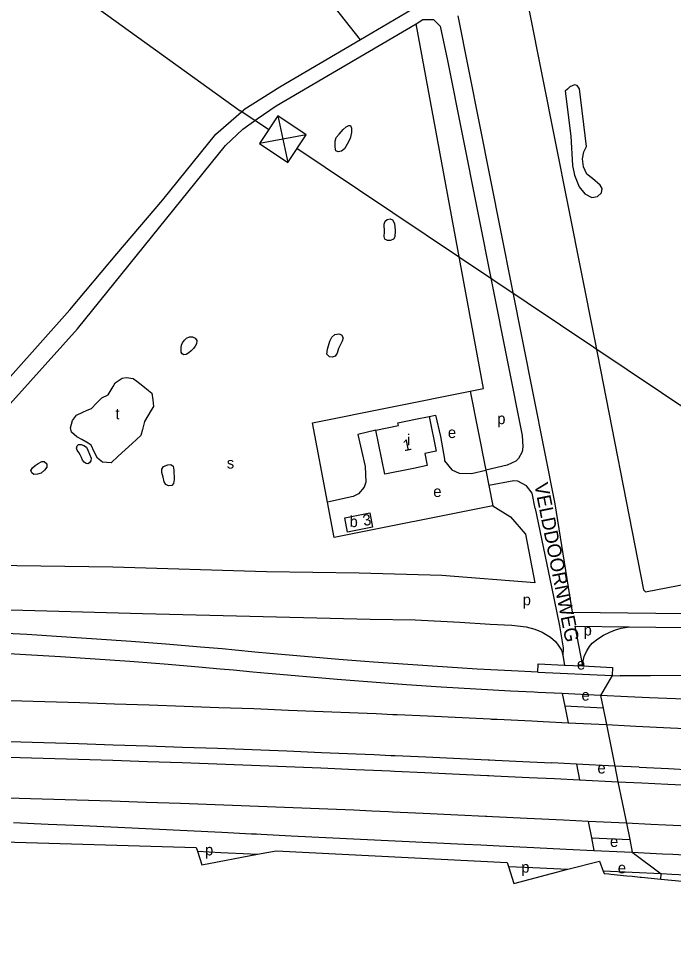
# Model space of a CAD drawing. Extents: x 160204 to 161526, y 379528 to 381793.
# Drawn here: x 160776.3 to 161011.9, y 379542.4 to 379877.4 of the extents above; entities that cross this region are included whole.
import ezdxf

# ---------------------------------------------------------------- set-up
doc = ezdxf.new("R2010")
doc.units = 0
for name, color, linetype in [('BLT_Basislijn', 7, 'Continuous'), ('BLT_Bebouwing', 7, 'Continuous'), ('BLT_Centroide', 7, 'Continuous'), ('BLT_Gemeentegrens', 7, 'Continuous'), ('BLT_Hoogspanningsmast_en_leidingen', 7, 'Continuous'), ('BLT_Huisnummer', 7, 'Continuous'), ('BLT_Straatnaam', 7, 'Continuous'), ('BLT_Vlakafsluiter', 7, 'Continuous')]:
    doc.layers.add(name, color=color, linetype=linetype)

msp = doc.modelspace()

# ---------------------------------------------------------------- linework, layer by layer
at = {"layer": 'BLT_Basislijn'}
for p, q in [((160934.43, 379878.45), (160969.28, 379702.73)), ((160943.64, 379744.33), (160919.34, 379875.6)), ((160810.28, 379744.96), (160811.1, 379746.33)), ((160811.1, 379746.33), (160813.58, 379747.98)), ((160813.58, 379747.98), (160815.17, 379748.29)), ((160815.17, 379748.29), (160817.56, 379747.91)), ((160817.56, 379747.91), (160818.86, 379746.88)), ((160818.86, 379746.88), (160820.95, 379745.23)), ((160808.56, 379742.07), (160810.28, 379744.96)), ((160820.95, 379745.23), (160823.04, 379743.58)), ((160823.04, 379743.58), (160824.29, 379742.6)), ((160824.29, 379742.6), (160824.57, 379740.22)), ((160882.02, 379731.98), (160938.84, 379743.37)), ((160938.84, 379743.37), (160943.64, 379744.33)), ((160938.84, 379743.37), (160944.44, 379714.95)), ((160804.37, 379739.05), (160806.22, 379740.98)), ((160806.22, 379740.98), (160808.56, 379742.07)), ((160824.57, 379740.22), (160824.84, 379737.84)), ((160799.43, 379735.75), (160800.98, 379736.44)), ((160800.98, 379736.44), (160802.53, 379737.12)), ((160802.53, 379737.12), (160804.37, 379739.05)), ((160824.02, 379736.44), (160822.82, 379734.41)), ((160824.84, 379737.84), (160824.02, 379736.44)), ((160795, 379730.16), (160795.65, 379732.73)), ((160795.65, 379732.73), (160797.09, 379734.72)), ((160797.09, 379734.72), (160799.43, 379735.75)), ((160822.82, 379734.41), (160821.63, 379732.38)), ((160795.3, 379728.61), (160795, 379730.16)), ((160820.86, 379729.5), (160820.28, 379727.34)), ((160821.63, 379732.38), (160820.86, 379729.5)), ((160887.41, 379703.39), (160882.02, 379731.98)), ((160797.23, 379726.89), (160795.3, 379728.61)), ((160799.08, 379725.97), (160797.23, 379726.89)), ((160801.35, 379724.56), (160799.08, 379725.97)), ((160818.73, 379725.93), (160817.18, 379724.52)), ((160820.28, 379727.34), (160818.73, 379725.93)), ((160802.45, 379723.87), (160801.35, 379724.56)), ((160803.55, 379721.54), (160802.45, 379723.87)), ((160817.18, 379724.52), (160814.64, 379722.21)), ((160804.65, 379719.2), (160803.55, 379721.54)), ((160806.5, 379717.83), (160804.65, 379719.2)), ((160812.1, 379719.9), (160809.56, 379717.59)), ((160814.64, 379722.21), (160812.1, 379719.9)), ((160809.56, 379717.59), (160806.5, 379717.83)), ((160944.44, 379714.95), (160945.54, 379709.34)), ((160945.54, 379709.34), (160946.98, 379702.01)), ((160969.28, 379702.73), (160975.53, 379663.75)), ((160976.43, 379658.74), (160979.24, 379644.43)), ((160963.12, 379642.17), (160989.94, 379641.02)), ((160989.94, 379641.02), (160992.79, 379640.9)), ((160971.9, 379634.47), (160963.12, 379634.9)), ((160971.9, 379634.47), (160972.82, 379629.92)), ((160985.69, 379633.8), (160971.9, 379634.47)), ((160995.45, 379633.32), (160985.69, 379633.8)), ((160985.69, 379633.8), (160986.62, 379629.25)), ((160986.62, 379629.25), (160972.82, 379629.92)), ((160972.82, 379629.92), (160974.02, 379624)), ((160986.62, 379629.25), (160987.82, 379623.33)), ((160965.04, 379624.44), (160974.02, 379624)), ((160974.02, 379624), (160987.82, 379623.33)), ((160987.82, 379623.33), (160996.42, 379622.91)), ((160977.05, 379609.09), (160968.23, 379609.52)), ((160977.05, 379609.09), (160978.21, 379603.42)), ((160990.85, 379608.41), (160977.05, 379609.09)), ((160999.68, 379607.98), (160990.85, 379608.41)), ((160990.85, 379608.41), (160992, 379602.75)), ((160969.11, 379603.87), (160978.21, 379603.42)), ((160978.21, 379603.42), (160992, 379602.75)), ((160992, 379602.75), (161000.6, 379602.33)), ((160981.24, 379588.51), (160972.36, 379588.94)), ((160981.24, 379588.51), (160982.44, 379582.59)), ((160995.03, 379587.84), (160981.24, 379588.51)), ((161003.8, 379587.41), (160995.03, 379587.84)), ((160995.03, 379587.84), (160996.23, 379581.92)), ((160982.44, 379582.59), (160996.23, 379581.92)), ((160982.44, 379582.59), (160983.36, 379578.04)), ((160996.23, 379581.92), (160997.16, 379577.37)), ((160973.37, 379578.53), (160983.36, 379578.04)), ((160983.36, 379578.04), (160997.16, 379577.37)), ((160997.16, 379577.37), (161005.73, 379576.95)), ((161007.53, 379569.61), (160986.7, 379570.62))]:
    msp.add_line(p, q, dxfattribs=at)
for points in [[(160899.34, 379869.75), (160838.56, 379946.96), (160831.95, 379953.52), (160783.95, 379999.78)], [(160916.02, 379935.16), (160925.3, 379888.11), (160925.28, 379886.57), (160924.22, 379884.76), (160921.8, 379882.93), (160899.34, 379869.75)], [(160959.88, 379880.87), (160983.6, 379762), (161001.22, 379671.83), (161001.95, 379671.12), (161047.14, 379679.9)], [(160919.34, 379875.6), (160921.8, 379877.04), (160925.63, 379877.11), (160928, 379874.75), (160930.71, 379862.36), (160957.56, 379727.33), (160957.79, 379723.3), (160957.55, 379721.48), (160956.15, 379719.16), (160955.2, 379718.2), (160952.08, 379716.73), (160944.44, 379714.95)], [(160862.11, 379841.36), (160868.99, 379846.06), (160919.34, 379875.6)], [(160899.34, 379869.75), (160870.36, 379852.74), (160857.41, 379844.61)], [(160686.29, 379682.82), (160737.48, 379711.91), (160746.25, 379719.03), (160752.91, 379725.65), (160794.74, 379772.59), (160811.69, 379792.71), (160828.15, 379812.23), (160847.28, 379835.89), (160857.41, 379844.61)], [(160714.73, 379691.69), (160729.47, 379699.34), (160740.52, 379706.54), (160746.8, 379711.17), (160757.2, 379721.03), (160797.44, 379765.72), (160850.78, 379831.75), (160856.96, 379837.67), (160862.11, 379841.36)], [(160924.04, 379734.22), (160926.38, 379734.71), (160928.09, 379727.02), (160929.54, 379718.81), (160929.59, 379718.22), (160932.2, 379714.99), (160934.9, 379713.77), (160939.27, 379713.74), (160944.44, 379714.95)], [(160904.87, 379729.29), (160898.39, 379727.75), (160900.97, 379716.2), (160901.23, 379710.57), (160900.65, 379708.82), (160898.58, 379706.34), (160896.74, 379705.38), (160887.41, 379703.39)], [(160962.24, 379701.07), (160961.18, 379706.59), (160959.08, 379709.32), (160955.99, 379710.92), (160954.56, 379711.03), (160945.54, 379709.34)], [(160946.98, 379702.01), (160889.82, 379690.64), (160887.41, 379703.39)], [(160946.98, 379702.01), (160953.36, 379698.08), (160958.67, 379691.87), (160962.04, 379674.37)], [(160962.24, 379701.07), (160968.14, 379672.96), (160970.93, 379658.91), (160972.28, 379650.99), (160972.17, 379648.23)], [(160962.04, 379674.37), (160928.58, 379676.98), (160898.9, 379677.88), (160865.48, 379678.32), (160810.17, 379679.97), (160775.69, 379680.42), (160734.32, 379681.17), (160697.47, 379682.72)], [(160975.53, 379663.75), (161005.65, 379663.43), (161049.95, 379662.91), (161061.02, 379662.97), (161065.81, 379663.17), (161069.15, 379663.77), (161073.72, 379664.97), (161078.31, 379666.46), (161085.6, 379669.78), (161098.15, 379675.54), (161108.55, 379680.23)], [(160563.17, 379668.7), (160589.01, 379668.81), (160613.98, 379668.38), (160632.18, 379668.08), (160662.14, 379666.95), (160686.53, 379666.48), (160709.05, 379665.91), (160737.95, 379665.26), (160769.1, 379664.77), (160820.86, 379663.28), (160849.87, 379662.62), (160902.88, 379661.28), (160918.99, 379661), (160935.1, 379660.15), (160946.02, 379659.49), (160953.84, 379659.12), (160958.98, 379658.56), (160962.1, 379657.7), (160964.74, 379656.63), (160967.7, 379654.85), (160969.48, 379653.29), (160970.5, 379651.89), (160971.63, 379650.06), (160972.17, 379648.23)], [(160963.12, 379642.17), (160953.74, 379642.63), (160941.3, 379643.32), (160928.86, 379644.08), (160916.43, 379644.91), (160904, 379645.81), (160891.57, 379646.79), (160879.16, 379647.83), (160866.75, 379648.94), (160861.29, 379649.45), (160854.29, 379650.11), (160849.51, 379650.54), (160841.81, 379651.22), (160829.31, 379652.26), (160816.81, 379653.23), (160804.3, 379654.13), (160791.79, 379654.96), (160779.28, 379655.72), (160766.76, 379656.4), (160754.23, 379657.02), (160741.71, 379657.56), (160735.68, 379657.79)], [(160976.43, 379658.74), (160996.04, 379658.53)], [(160979.24, 379644.43), (160979.45, 379646.22), (160979.88, 379647.78), (160980.68, 379649.6), (160981.76, 379651.42), (160982.77, 379652.68), (160984.8, 379654.18), (160986.8, 379655.51), (160989.05, 379656.61), (160991.06, 379657.38), (160993.12, 379657.98), (160996.04, 379658.53)], [(160996.04, 379658.53), (161005.59, 379658.43), (161049.93, 379657.91), (161061.14, 379657.97), (161066.36, 379658.19)], [(160963.12, 379634.9), (160961.89, 379634.95), (160953.36, 379635.39), (160940.88, 379636.08), (160928.4, 379636.84), (160915.92, 379637.68), (160903.45, 379638.58), (160890.99, 379639.56), (160878.53, 379640.61), (160866.08, 379641.72), (160860.61, 379642.24), (160853.63, 379642.89), (160848.86, 379643.32), (160841.18, 379644), (160828.73, 379645.04), (160816.27, 379646), (160803.8, 379646.9), (160791.33, 379647.73), (160778.86, 379648.48), (160766.38, 379649.16), (160753.9, 379649.78), (160741.41, 379650.32), (160735.33, 379650.55)], [(160972.17, 379648.23), (160972.71, 379644.76)], [(160963.12, 379642.17), (160963.28, 379645.23), (160972.71, 379644.76)], [(160972.71, 379644.76), (160979.24, 379644.43)], [(160979.24, 379644.43), (160990.08, 379643.88), (160989.94, 379641.02)], [(161016.13, 379640.98), (161003.66, 379640.91), (160994.54, 379640.9), (160992.79, 379640.9)], [(161015.79, 379632.43), (161003.3, 379632.96), (160995.45, 379633.32)], [(160773.26, 379631.97), (160785.78, 379631.61), (160798.3, 379631.23), (160810.82, 379630.84), (160823.34, 379630.43), (160835.86, 379629.99), (160848.38, 379629.54), (160860.9, 379629.07), (160873.41, 379628.58), (160885.93, 379628.07), (160898.45, 379627.55), (160904.94, 379627.27), (160910.96, 379627), (160912.48, 379626.93), (160923.47, 379626.43), (160935.99, 379625.85), (160946.02, 379625.37), (160946.47, 379625.34), (160948.49, 379625.25), (160960.98, 379624.64), (160965.04, 379624.44)], [(160996.42, 379622.91), (160998.43, 379622.81), (161010.92, 379622.2), (161018.91, 379621.81), (161023.41, 379621.59), (161035.89, 379620.99), (161048.38, 379620.38), (161060.86, 379619.77), (161073.35, 379619.16), (161085.83, 379618.55), (161095.97, 379618.06), (161098.32, 379617.94), (161110.8, 379617.33), (161123.29, 379616.73), (161135.77, 379616.12), (161148.26, 379615.51), (161160.74, 379614.9), (161173.23, 379614.29), (161173.36, 379614.29), (161185.71, 379613.68), (161198.02, 379613.08)], [(160772.85, 379617.22), (160785.35, 379616.87), (160797.85, 379616.49), (160810.35, 379616.1), (160822.84, 379615.69), (160835.34, 379615.25), (160847.84, 379614.8), (160860.33, 379614.33), (160872.83, 379613.85), (160885.32, 379613.34), (160897.81, 379612.81), (160904.3, 379612.53), (160910.31, 379612.26), (160911.82, 379612.2), (160922.8, 379611.7), (160935.29, 379611.12), (160945.3, 379610.63), (160945.75, 379610.61), (160947.78, 379610.51), (160960.26, 379609.9), (160968.23, 379609.52)], [(160772.69, 379611.62), (160785.18, 379611.27), (160797.68, 379610.89), (160810.16, 379610.5), (160822.65, 379610.09), (160835.14, 379609.66), (160847.63, 379609.21), (160860.12, 379608.74), (160872.6, 379608.25), (160885.09, 379607.74), (160897.57, 379607.22), (160904.05, 379606.93), (160910.06, 379606.67), (160911.57, 379606.6), (160922.54, 379606.11), (160935.02, 379605.52), (160945.03, 379605.04), (160945.48, 379605.02), (160947.5, 379604.92), (160959.99, 379604.31), (160969.11, 379603.87)], [(160999.68, 379607.98), (161010.2, 379607.47), (161018.19, 379607.08), (161022.69, 379606.86), (161035.17, 379606.25), (161047.66, 379605.64), (161060.14, 379605.04), (161072.63, 379604.43), (161085.11, 379603.82), (161095.25, 379603.32), (161097.6, 379603.21), (161110.08, 379602.6), (161122.57, 379601.99), (161135.05, 379601.38), (161147.54, 379600.78), (161160.02, 379600.17), (161172.51, 379599.56), (161172.64, 379599.55), (161184.99, 379598.95), (161197.48, 379598.34), (161198.05, 379598.31)], [(161000.6, 379602.33), (161009.93, 379601.88), (161017.92, 379601.49), (161022.41, 379601.27), (161034.9, 379600.66), (161047.38, 379600.05), (161059.87, 379599.44), (161072.36, 379598.83), (161084.84, 379598.23), (161094.98, 379597.73), (161097.33, 379597.62), (161109.81, 379597.01), (161122.3, 379596.4), (161134.78, 379595.79), (161147.27, 379595.18), (161159.75, 379594.57), (161172.24, 379593.97), (161172.37, 379593.96), (161184.72, 379593.36), (161197.21, 379592.75), (161198, 379592.71)], [(160972.36, 379588.94), (160959.27, 379589.58), (160946.79, 379590.19), (160944.76, 379590.29), (160944.31, 379590.31), (160934.32, 379590.79), (160921.86, 379591.37), (160910.91, 379591.87), (160909.4, 379591.93), (160903.41, 379592.2), (160896.94, 379592.48), (160884.48, 379593), (160872.01, 379593.51), (160859.55, 379594), (160847.09, 379594.47), (160834.62, 379594.92), (160822.16, 379595.35), (160809.69, 379595.76), (160797.22, 379596.15), (160784.75, 379596.52), (160772.29, 379596.88)], [(160774.49, 379588.07), (160786.98, 379587.55), (160799.47, 379586.99), (160811.95, 379586.4), (160812.02, 379586.39), (160824.44, 379585.79), (160836.93, 379585.18), (160849.41, 379584.57), (160860.13, 379584.05), (160861.9, 379583.96), (160863.59, 379583.88), (160874.38, 379583.35), (160886.87, 379582.75), (160899.35, 379582.14), (160911.84, 379581.53), (160924.32, 379580.92), (160936.81, 379580.31), (160942.69, 379580.02), (160949.29, 379579.7), (160961.78, 379579.09), (160973.37, 379578.53)], [(161198.04, 379577.94), (161196.49, 379578.02), (161184, 379578.62), (161171.65, 379579.23), (161171.52, 379579.23), (161159.03, 379579.84), (161146.55, 379580.45), (161134.06, 379581.06), (161121.58, 379581.67), (161109.09, 379582.28), (161096.61, 379582.88), (161094.26, 379583), (161084.12, 379583.49), (161071.64, 379584.1), (161059.15, 379584.71), (161046.67, 379585.32), (161034.18, 379585.93), (161021.7, 379586.54), (161017.2, 379586.75), (161009.21, 379587.14), (161003.8, 379587.41)], [(160840.69, 379577.74), (160849.06, 379577.33), (160859.78, 379576.81), (160862.3, 379576.68)], [(161005.73, 379576.95), (161008.08, 379576.84), (161011.72, 379576.66), (161024.2, 379575.99), (161036.68, 379575.26), (161049.16, 379574.45), (161061.63, 379573.57), (161074.1, 379572.62), (161082.32, 379571.96), (161086.56, 379571.6), (161099.01, 379570.51), (161111.46, 379569.35), (161111.81, 379569.32), (161123.91, 379568.19), (161136.36, 379567.1), (161148.81, 379566.07), (161161.27, 379565.12), (161173.74, 379564.24), (161186.21, 379563.43), (161196.61, 379562.8)], [(160952.57, 379572.28), (160961.42, 379571.85), (160973.96, 379571.24)], [(161007.45, 379567.75), (161007.53, 379569.61)], [(161198.12, 379551.84), (161185.32, 379552.66), (161185.05, 379552.68), (161172.84, 379553.48), (161160.37, 379554.36), (161147.9, 379555.31), (161135.44, 379556.33), (161125.43, 379557.21), (161122.94, 379557.55), (161110.84, 379559.26), (161110.5, 379559.31), (161098.16, 379561.05), (161085.81, 379562.73), (161081.6, 379563.28), (161073.44, 379564.33), (161061.07, 379565.87), (161051.16, 379567.05), (161048.67, 379567.22), (161036.24, 379568.02), (161023.8, 379568.75), (161011.35, 379569.42), (161007.72, 379569.6), (161007.53, 379569.61)]]:
    msp.add_lwpolyline(points, dxfattribs=at)
for points in [[(160973.03, 379851.28), (160975.02, 379835.16), (160975.62, 379824.52), (160976.34, 379821.02), (160978.02, 379816.85), (160980.06, 379814.31), (160982.6, 379813), (160984.64, 379813.4), (160986.04, 379814.67), (160986.27, 379816.22), (160985.59, 379817.49), (160982.78, 379819.85), (160980.84, 379821.47), (160979.61, 379824.11), (160979.2, 379826.92), (160979.74, 379829.51), (160980.65, 379831.37), (160978.13, 379852.1), (160977.28, 379853.4), (160976.41, 379853.53), (160974.73, 379852.84), (160973.79, 379851.98)], [(160891.65, 379835.87), (160893.09, 379837.5), (160894.17, 379838.43), (160895.1, 379838.98), (160895.73, 379838.9), (160896.15, 379837.97), (160896.11, 379836.49), (160895.57, 379834.28), (160894.6, 379832.19), (160893.55, 379830.59), (160892.46, 379829.74), (160891.26, 379829.47), (160890.48, 379829.86), (160890.21, 379831.18), (160890.17, 379833.27), (160890.64, 379834.63)], [(160907.84, 379803.42), (160908.18, 379804.51), (160908.88, 379805.09), (160910.01, 379805.4), (160910.9, 379804.94), (160911.56, 379803.62), (160911.87, 379801.21), (160911.72, 379798.92), (160911.17, 379797.99), (160910.09, 379797.52), (160909.04, 379797.52), (160908.07, 379798.03), (160907.91, 379799.04), (160907.99, 379800.71)], [(160835.27, 379760.72), (160835.95, 379761.71), (160836.71, 379762.43), (160837.85, 379762.92), (160838.94, 379762.94), (160839.89, 379762.41), (160840.43, 379761.56), (160840.33, 379760.36), (160839.87, 379759.52), (160839.25, 379758.65), (160838.39, 379757.85), (160837.56, 379757.1), (160836.61, 379756.57), (160835.75, 379756.45), (160835.15, 379756.8), (160834.86, 379757.35), (160834.78, 379758.26), (160834.86, 379759.11), (160834.96, 379759.85)], [(160888.27, 379761.38), (160889.05, 379762.74), (160890.06, 379763.67), (160891.53, 379764.02), (160892.54, 379763.6), (160893.12, 379762.55), (160892.7, 379761.38), (160891.38, 379758.71), (160890.95, 379757), (160890.25, 379755.95), (160889.2, 379755.56), (160888.16, 379755.64), (160887.19, 379756.61), (160887.42, 379758.51)], [(160797.36, 379723.66), (160797.89, 379724.12), (160798.78, 379724.16), (160799.73, 379723.83), (160800.68, 379723.15), (160801.21, 379722.12), (160802.37, 379719.21), (160802.28, 379718.24), (160801.81, 379717.56), (160801.21, 379717.23), (160800.57, 379717.29), (160799.87, 379717.81), (160799.34, 379718.55), (160798.98, 379719.44), (160798.45, 379720.43), (160797.95, 379721.25), (160797.36, 379722.06), (160797.15, 379722.86)], [(160782.28, 379716.61), (160783.38, 379717.33), (160784.61, 379717.98), (160785.46, 379718.08), (160786.43, 379717.15), (160786.43, 379716.03), (160785.61, 379714.86), (160784.41, 379713.82), (160783.05, 379713.43), (160781.77, 379713.31), (160781.11, 379713.89), (160780.72, 379714.82), (160781.3, 379715.76)], [(160828.42, 379716.2), (160830.01, 379716.86), (160831.06, 379716.9), (160831.95, 379716.32), (160832.22, 379714.88), (160832.34, 379711.51), (160832.07, 379710.07), (160831.48, 379709.33), (160830.28, 379709.25), (160829.23, 379709.76), (160828.65, 379710.73), (160828.38, 379712.36), (160827.87, 379714.03), (160827.87, 379715.23)]]:
    msp.add_lwpolyline(points, close=True, dxfattribs=at)
at = {"layer": 'BLT_Bebouwing'}
for points in [[(160904.87, 379729.29), (160913.01, 379730.93), (160912.8, 379731.95), (160919.14, 379733.23), (160924.04, 379734.22)], [(160924.04, 379734.22), (160926.56, 379721.73), (160922.46, 379720.9), (160923.34, 379716.55), (160918.44, 379715.55), (160908.07, 379713.46), (160904.87, 379729.29)]]:
    msp.add_lwpolyline(points, dxfattribs=at)
msp.add_lwpolyline([(160893.65, 379697.75), (160902.69, 379699.55), (160903.71, 379694.42), (160894.67, 379692.62)], close=True, dxfattribs=at)
at = {"layer": 'BLT_Gemeentegrens'}
for points in [[(160758.54, 379581.44), (160840.25, 379579.13), (160840.69, 379577.74)], [(160840.69, 379577.74), (160842.22, 379572.89), (160862.3, 379576.68)], [(160862.3, 379576.68), (160868.95, 379577.94), (160952.14, 379573.66), (160952.57, 379572.28)], [(160952.57, 379572.28), (160954.48, 379566.17), (160973.96, 379571.24)], [(160973.96, 379571.24), (160985.39, 379574.22), (160986.7, 379570.62)], [(160986.7, 379570.62), (160987.02, 379569.76), (160988.67, 379569.6), (160989.42, 379569.52), (160995.21, 379568.95), (160997.08, 379568.76), (161000, 379568.47), (161000.43, 379568.43), (161007.45, 379567.75)], [(161007.45, 379567.75), (161035.45, 379565.05), (161090.09, 379559.76), (161098.34, 379558.49), (161202.18, 379542.43)]]:
    msp.add_lwpolyline(points, dxfattribs=at)
at = {"layer": 'BLT_Hoogspanningsmast_en_leidingen'}
for p, q in [((160700, 379956.75), (160856.09, 379844.25)), ((160866.28, 379837.46), (160856.09, 379844.25)), ((160869.6, 379842.44), (160873.15, 379825.69)), ((160879.79, 379835.65), (160862.96, 379832.48)), ((160886.66, 379823.88), (160876.47, 379830.67)), ((161125.87, 379663.46), (160886.66, 379823.88))]:
    msp.add_line(p, q, dxfattribs=at)
msp.add_lwpolyline([(160862.96, 379832.48), (160873.15, 379825.69), (160879.79, 379835.65), (160869.6, 379842.44)], close=True, dxfattribs=at)
at = {"layer": 'BLT_Vlakafsluiter'}
for p, q in [((160989.94, 379641.02), (160985.69, 379633.8)), ((160987.82, 379623.33), (160990.85, 379608.41)), ((160992, 379602.75), (160995.03, 379587.84)), ((160997.16, 379577.37), (161007.53, 379569.61))]:
    msp.add_line(p, q, dxfattribs=at)

# ---------------------------------------------------------------- texts
at = {"layer": 'BLT_Centroide'}
for s, p in [('t', (160811.14, 379733.21)), ('p', (160948.55, 379731.47)), ('e', (160930.79, 379726.46)), ('i', (160916.05, 379723.84)), ('s', (160851.22, 379715.48)), ('e', (160925.53, 379705.24)), ('b', (160895.4, 379694.41)), ('p', (160957.7, 379666.28)), ('p', (160979.62, 379655.39)), ('e', (160977.22, 379643.14)), ('e', (160978.86, 379631.96)), ('e', (160984.61, 379605.75)), ('e', (160989.13, 379579.3)), ('p', (160843.37, 379576.25)), ('p', (160957.18, 379570.05)), ('e', (160991.94, 379569.79))]:
    msp.add_text(s, height=4, dxfattribs=at).set_placement(p)
at = {"layer": 'BLT_Huisnummer'}
for s, rotation, p in [('1', 11.4289, (160915.01, 379721.69)), ('3', 10.4077, (160900.55, 379694.78))]:
    msp.add_text(s, height=4, rotation=rotation, dxfattribs=at).set_placement(p)
at = {"layer": 'BLT_Straatnaam'}
msp.add_text('VELDDOORNWEG', height=5, rotation=281.249, dxfattribs=at).set_placement((160961.85, 379709.85))

doc.saveas('drawing.dxf')
